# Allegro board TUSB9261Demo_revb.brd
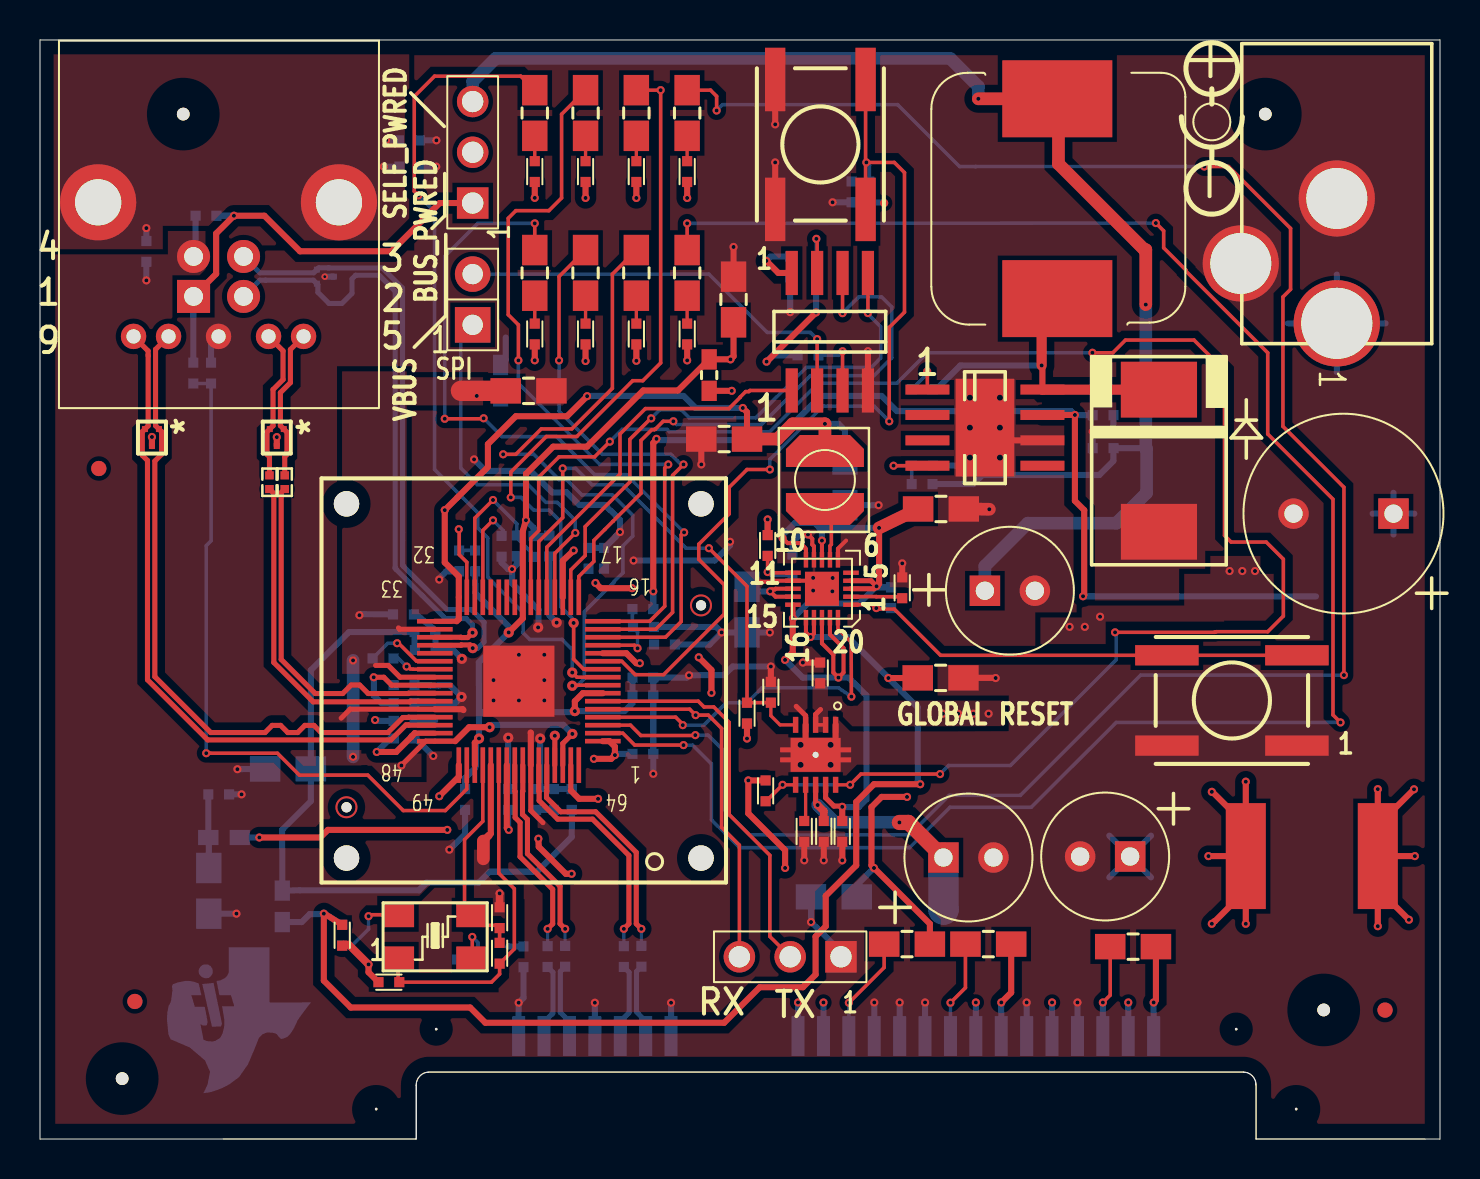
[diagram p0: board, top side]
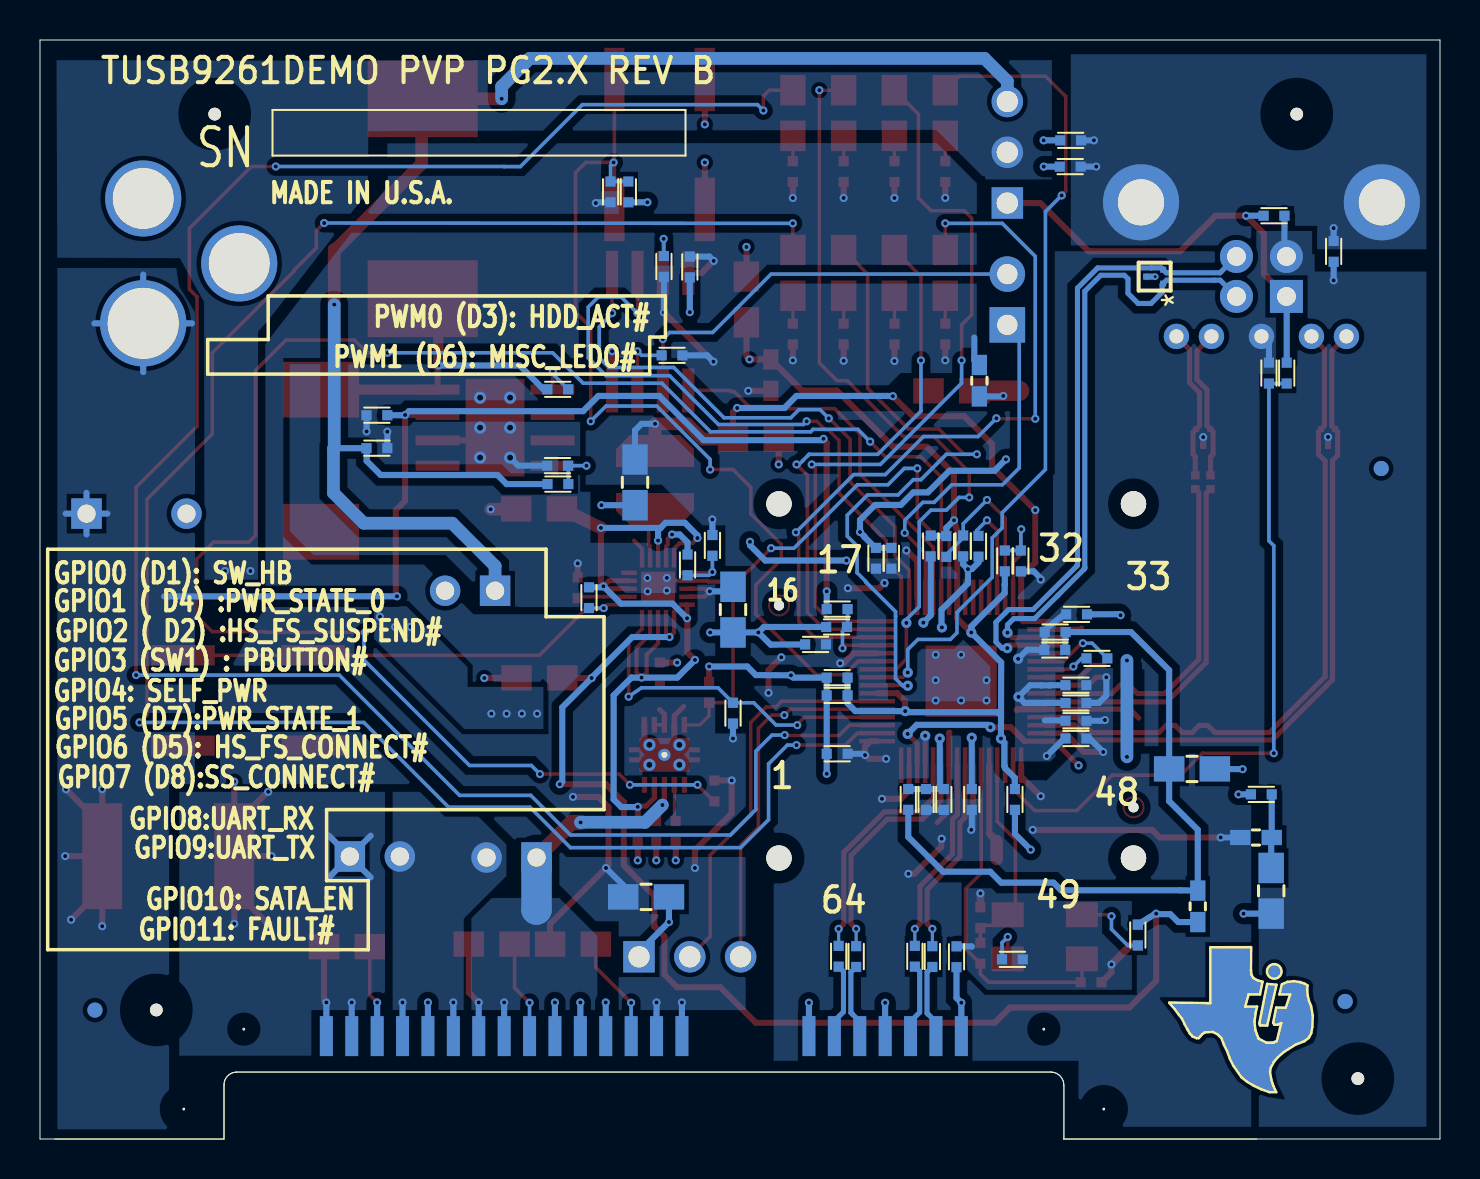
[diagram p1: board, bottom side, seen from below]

Outline 70 x 55 mm; copper layers: TOP, BOTTOM. Coordinates in mm from the lower left corner of the outline.
Outline path: 0,55 0,0 18.81,0 18.81,2.69 arc(18.98,3.14) 19.42,3.35 60.18,3.35 arc(60.62,3.16) 60.79,2.72 60.79,0 70,0 70,55 0,55

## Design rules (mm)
net group DIFFPAIR0: nets CAP_SSTXM CAP_SSTXP
net group DIFFPAIR1: nets SSTXM SSTXP
net group DIFFPAIR2: nets SSRXM SSRXP
net group DIFFPAIR3: nets CAP_SATARXM CAP_SATARXP
net group DIFFPAIR4: nets SATARXM SATARXP
net group DIFFPAIR5: nets CAP_SATATXM CAP_SATATXP
net group DIFFPAIR6: nets SATATXM SATATXP
net group DIFFPAIR7: nets US_DM US_DP

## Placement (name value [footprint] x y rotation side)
C1  0.01uF  [0402]  25.38 9.13 90 bottom
C2  0.01uF  [0402]  26.26 9.15 90 bottom
C6  0.01uF  [0402]  29.19 9.13 90 bottom
C7  0.01uF  [0402]  30.07 9.15 90 bottom
C8  22uF  [0805]  39.7 12.12 180 bottom
C10  220uF  [THCAP_2P5MM]  45.17 14.09 0 top
C11  0.1uF  [0402]  37.51 43.64 270 bottom
C12  220uF  [THCAP_2P5MM]  54.51 14.14 180 top
C13  0.1uF  [0201]  12.24 32.87 270 top
C14  0.1uF  [0201]  11.47 32.87 270 top
C15  .1uF  [0402]  5.32 44.42 90 bottom
C16  .001uF  [0402]  18.47 49.98 180 bottom
C17  18pF  [0402]  17.44 7.85 180 top
C18  0.1uF  [0402]  15.11 10.2 270 top
C19  18pF  [0402]  22.98 11.08 90 top
C20  18pF  [0402]  40.58 47.4 90 bottom
C21  220uF  [THCAP_2P5MM]  47.24 27.44 0 top
C22  0.01uF  [0402]  53.16 34.57 0 bottom
C23  0.01uF  [0402]  44.11 37.52 0 bottom
C24  22uF  [0805]  34.68 42.01 90 top
C25  1uF  [0402]  25.46 29.68 270 bottom
C26  0.1uF  [0402]  21.25 16.99 270 bottom
C27  0.1uF  [0402]  30.14 23.09 0 bottom
C28  0.1uF  [0402]  30.14 22.2 0 bottom
C29  0.01uF  [0402]  53.16 36.22 180 bottom
C30  1000uF  [THCAP_5MM]  65.17 31.3 180 top
C31  0.1uF  [0402]  18.17 26.25 0 bottom
C32  22uF  [0805]  24.43 37.44 0 top
C33  22uF  [0805]  34.21 35.03 180 top
C34  1uF  [0402]  31.22 24.75 0 bottom
C35  0.1uF  [0402]  18.21 21.82 0 bottom
C36  0.1uF  [0402]  30.14 19.28 0 bottom
C37  0.1uF  [0402]  24.81 16.99 90 bottom
C38  0.01uF  [0402]  23.41 16.99 90 bottom
C39  0.1uF  [0402]  27.43 29.06 90 bottom
C40  0.1uF  [0402]  25.7 16.99 90 bottom
C41  0.1uF  [0402]  28.2 29.06 90 bottom
C42  0.01uF  [0402]  18.21 22.71 0 bottom
C43  0.1uF  [0402]  18.21 20.93 0 bottom
C44  0.1uF  [0402]  18.21 20.04 0 bottom
C45  1uF  [0402]  8.3 46.2 180 bottom
C46  22uF  [0805]  40.25 32.86 270 bottom
C54  0.1uF  [0402]  8.93 17.25 0 bottom
C57  22uF  [0805]  45.05 31.53 0 top
C58  0.1uF  [0402]  19.26 24.47 0 bottom
C59  0.01uF  [0402]  26.59 16.99 90 bottom
C60  22uF  [0805]  35.35 26.49 270 bottom
C61  1uF  [0402]  19.24 25.37 0 bottom
C62  22uF  [0805]  12.4 18.52 180 bottom
C63  22uF  [0805]  45.03 23.08 0 top
C64  22uF  [0805]  8.44 12.42 270 bottom
C66  0.1uF  [0402]  39.01 23.32 90 top
C67  0.1uF  [0402]  40.11 15.4 270 top
C68  0.1uF  [0402]  43.11 27.59 90 top
C69  0.1uF  [0402]  39.19 15.4 270 top
C72  30pF  [0402]  36.38 29.71 90 bottom
CN1  10031569-001LF  [CONN_10031569]  39.81 5.15 180 bottom
D1  LED Green 0805  [0805]  29.82 43.34 90 top
D2  LED Green 0805  [0805]  29.82 51.35 90 top
D3  LED Green 0805  [0805]  32.36 43.34 90 top
D4  LED Green 0805  [0805]  24.74 51.35 90 top
D5  LED Green 0805  [0805]  27.28 43.34 90 top
D6  LED Green 0805  [0805]  32.36 51.35 90 top
D7  LED Green 0805  [0805]  24.74 43.34 90 top
D8  LED Green 0805  [0805]  27.28 51.35 90 top
D12  MBRS540T3  [DIODE_SMC]  55.95 33.94 270 top
F1  PTC FUSE  [FUSE_2920L]  63.59 14.16 0 top
FB1  220 @ 100MHZ  [0603]  33.46 38.23 90 top
FB2  220 @ 100MHZ  [0603]  23.03 37.95 270 bottom
FB4  220 @ 100MHZ  [0603]  9.2 15.09 180 bottom
FB5  220 @ 100MHZ  [0603]  12.11 11.64 90 bottom
J1  NOPOP  [EPRT-HEAD-00001-0000]  40.05 9.12 180 top
J2  Conn USB3_B_AK  [USB3_TYPEB_AK4AA009]  7.68 42.17 180 top
J3  2.1mm x 5.5mm  [PJ-202AH]  64.84 40.82 180 top
J4  HDR  [EPRT-HEAD-00001-0000]  21.63 46.84 90 top
J13  HDR2X1 M .1  [HDR_2X1]  21.63 40.74 0 top
L1  15uH  [DR127]  50.87 47.06 270 top
L2  2.2uH  [IND_SM_VLCF_4X4X2MM]  39.25 32.98 90 top
NOREF  -  [unnamed]  7.16 51.29 0 top
NOREF#2  -  [#2]  -0.04 0 90 top
NOREF#3  -  [unnamed]  4.11 3.02 0 top
NOREF#4  -  [unnamed#3]  67.25 6.45 0 top
NOREF#5  -  [#2]  -0.04 55 0 top
NOREF#6  -  [#2]  5.76 -42.8 0 top
NOREF#7  -  [unnamed]  64.19 6.46 0 top
NOREF#8  -  [#2]  51.15 0 90 top
NOREF#9  -  [#2]  16.81 1.5 0 top
NOREF#10  -  [#2]  45.25 29.97 0 top
NOREF#11  -  [unnamed#3]  4.74 6.88 0 top
NOREF#12  -  [#2]  -0.04 0 90 top
NOREF#13  -  [unnamed]  61.26 51.29 0 top
NOREF#14  -  [#2]  50.44 16.59 0 top
NOREF#15  -  [#2]  18.81 0 0 top
NOREF#16  -  [#2]  16.81 1.5 0 top
NOREF#17  -  [unnamed#3]  2.94 33.55 0 top
NOREF#18  -  [unnamed#3]  4.74 6.88 180 bottom
NOREF#19  -  [unnamed#3]  67.25 6.45 180 bottom
NOREF#20  -  [unnamed#3]  2.94 33.55 180 bottom
NOREF#21  -  [#2]  9.86 6.64 180 bottom
R2  4.7K  [0402]  38.4 39.22 0 bottom
R3  4.7K  [0402]  38.8 43.66 90 bottom
R4  10K  [0402]  17.15 24.05 0 bottom
R5  NOPOP  [0402]  23.08 29.66 90 bottom
R6  90.9K  [0402]  7.66 38.33 270 bottom
R7  10K  [0402]  8.55 38.33 270 bottom
R8  NOPOP  [0402]  22.98 9.3 90 top
R9  1M  [0402]  18.49 48.66 0 bottom
R10  4.7K  [0402]  24.68 29.65 90 bottom
R11  NOPOP  [0402]  23.84 29.68 270 bottom
R12  NOPOP  [0402]  21.76 28.93 270 bottom
R13  4.7K  [0402]  20.96 28.93 270 bottom
R14  330  [0402]  29.82 40.29 90 top
R15  330  [0402]  29.82 48.41 90 top
R16  330  [0402]  32.36 40.29 90 top
R17  4.7K  [0402]  41.47 47.4 90 bottom
R18  330  [0402]  24.74 48.41 90 top
R19  330  [0402]  27.28 40.29 90 top
R20  330  [0402]  32.36 48.41 90 top
R21  330  [0402]  24.74 40.29 90 top
R22  330  [0402]  27.28 48.41 90 top
R23  NOPOP  [0402]  15.11 10.21 270 bottom
R24  3.65K  [0402]  30.17 25.63 0 bottom
R25  10K  [0402]  30.14 26.52 180 bottom
R26  10K  [0402]  44.11 32.77 0 bottom
R27  3.16K  [0402]  44.13 33.7 180 bottom
R30  400K  [0402]  36.38 29.7 270 top
R31  475K  [0402]  37.62 28.73 270 bottom
R32  4.7K  [0402]  35.35 21.31 270 bottom
R33  10K  [0402]  36.28 17.42 270 top
R34  NOPOP  [0402]  35.35 21.31 270 top
R35  4.7K  [0402]  36.54 22.36 90 top
R36  27.4K  [0402]  38.21 15.4 270 top
R37  NOPOP  [0402]  21.38 8.99 180 bottom
R38  NOPOP  [0402]  24.17 9.12 270 bottom
R39  4.7K  [0402]  42.55 27.09 270 bottom
R40  10  [0805]  43.35 9.76 180 top
R41  10  [0805]  47.42 9.76 180 top
R42  10  [0805]  54.65 9.63 180 top
SW1  PB_SWITCH  [SW_MOM_2NO]  39.02 49.77 0 top
SW2  PB_SWITCH  [SW_MOM_2NO]  59.59 21.95 90 top
U2  Pm25LV512A  [SOIC_8S]  39.49 40.4 90 top
U3  TPS5450  [DDA_R-PDSO-G8]  47.25 35.6 0 top
U4  TPS650061  [RUK_S-PQFP-N20]  39.1 27.54 180 top
U5  TUSB9260APVP  [IRONWOOD_64PIN_C9508]  33.05 14.06 180 top
U7  TPS2560DRC  [DRC_S_PVSON_N10]  38.78 19.23 270 top
U10  TPD2EUSB30  [DRT_R_PDSO_N3_SOT23]  5.6 35.1 180 top
U11  TPD2EUSB30  [DRT_R_PDSO_N3_SOT23]  11.84 35.1 180 top
U12  TPD2EUSB30  [DRT_R_PDSO_N3_SOT23]  14.27 43.16 90 bottom
XY1  X OR Y  [ECX-53B]  19.76 10.12 0 top

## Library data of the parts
C1 C2 C6-C8 C11 C13-C20 C22-C29 C31-C46 C54 C57-C64 C66-C69 C72 = CAP NP
C10 C12 C21 C30 = CAP POL
CN1 = 0876781001: User Part Number: P*
D1-D8 = DIODE
D12 = DIODE SCHOTTKY
F1 = FUSE
FB1 FB2 FB4 FB5 = FERRITE BEAD
J1 J4 = HDR3X1 M .1
J2 = USB3_TYPEB_CONNECTOR
J3 = BNC_2
J13 = HDR2X1 M .1
L1 L2 = INDUCTOR FERRITE
NOREF#4 NOREF#11 NOREF#17-NOREF#20 = -: User Part Number: D*
R2-R27 R30-R42 = R
SW1 SW2 = PB_SWITCH_0
U2 = Pm25LV512A
U3 = TPS5450_2
U4 = TPS650061_0
U5 = TUSB9260PAP_6
U7 = TPS2560DRC_1
U10-U12 = TPD2E009
XY1 = X OR Y

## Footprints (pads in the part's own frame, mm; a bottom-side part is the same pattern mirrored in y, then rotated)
0201
  rect 0.406x0.432 smd: 1(-0.343,0) 2(0.343,0)
0402
  rect 0.508x0.508 smd: 1(-0.521,0) 2(0.521,0)
0603
  rect 1.016x0.762 smd: 1(-0.787,0) 2(0.787,0)
0805
  rect 1.524x1.27 smd: 1(-1.143,0) 2(1.143,0)
CONN_10031569
  round 0.127 hole 1.95 unplated: (-23,-3.65) (23,-3.65)
  round 0.127 hole 1.2 unplated: (-20,0.35) (20,0.35)
  rect 0.65x2 smd: P1(1.905,0) P2(0.635,0) P3(-0.635,0) P4(-1.905,0) P5(-3.175,0) P6(-4.445,0) P7(-5.715,0) P8(-6.985,0) P9(-8.255,0) P10(-9.525,0) P11(-10.795,0) P12(-12.065,0) P13(-13.335,0) P14(-14.605,0) P15(-15.875,0) S1(15.875,0) S2(14.605,0) S3(13.335,0) S4(12.065,0) S5(10.795,0) S6(9.525,0) S7(8.255,0)
DDA_R-PDSO-G8
  rect 2.2x0.5 smd: 1(-2.875,1.905) 2(-2.875,0.635) 3(-2.875,-0.635) 4(-2.875,-1.905) 5(2.875,-1.905) 6(2.875,-0.635) 7(2.875,0.635) 8(2.875,1.905)
  rect 2.94x4.89 smd: 9(0,0)
DIODE_SMC
  rect 2.794x3.81 smd: 1(3.556,0) 2(-3.556,0)
DR127
  rect 3.85x5.5 smd: 1(-5,0) 2(5,0)
DRC_S_PVSON_N10
  rect 0.8x0.27 smd: 1(-1.5,1) 2(-1.5,0.5) 3(-1.5,0) 4(-1.5,-0.5) 5(-1.5,-1) 6(1.5,-1) 7(1.5,-0.5) 8(1.5,0) 9(1.5,0.5) 10(1.5,1)
  round 0.61 hole 0.305: 11(0,0)
DRT_R_PDSO_N3_SOT23
  rect 0.3x0.3 smd: 1(-0.35,-0.425) 2(0.35,-0.425) 3(0,0.425)
ECX-53B
  rect 1.6x1.245 smd: 1(-1.854,-1.105) 2(1.854,-1.105) 3(1.854,1.105) 4(-1.854,1.105)
EPRT-HEAD-00001-0000
  rect 1.575x1.575 hole 1.067: 1(0,0)
  round 1.575 hole 1.067: 2(2.54,0) 3(5.08,0)
FUSE_2920L
  rect 2x5.3 smd: 1(-3.3,0) 2(3.3,0)
HDR_2X1
  rect 1.778x1.778 hole 1.016: 1(0,0)
  round 1.778 hole 1.016: 2(0,2.54)
IND_SM_VLCF_4X4X2MM
  custom 0.4x0.4 smd: 1(-1.45,0) 2(1.45,0)
IRONWOOD_64PIN_C9508
  round 1.27 hole 1.608 unplated: (0,0) (0,-17.725) (17.725,0) (17.725,-17.725)
  round 0.508 hole 0.848 unplated: (0,-12.646) (17.725,-2.54)
  rect 1.78x0.23 smd: 1(4.91,-5.85) 2(4.91,-6.25) 3(4.91,-6.65) 4(4.91,-7.05) 5(4.91,-7.45) 6(4.91,-7.85) 7(4.91,-8.25) 8(4.91,-8.65) 9(4.91,-9.05) 10(4.91,-9.45) 11(4.91,-9.85) 12(4.91,-10.25) 13(4.91,-10.65) 14(4.91,-11.05) 15(4.91,-11.45) 16(4.91,-11.85) 33(13.31,-11.85) 34(13.31,-11.45) 35(13.31,-11.05) 36(13.31,-10.65) 37(13.31,-10.25) 38(13.31,-9.85) 39(13.31,-9.45) 40(13.31,-9.05) 41(13.31,-8.65) 42(13.31,-8.25) 43(13.31,-7.85) 44(13.31,-7.45) 45(13.31,-7.05) 46(13.31,-6.65) 47(13.31,-6.25) 48(13.31,-5.85)
  rect 0.23x1.78 smd: 17(6.11,-13.05) 18(6.51,-13.05) 19(6.91,-13.05) 20(7.31,-13.05) 21(7.71,-13.05) 22(8.11,-13.05) 23(8.51,-13.05) 24(8.91,-13.05) 25(9.31,-13.05) 26(9.71,-13.05) 27(10.11,-13.05) 28(10.51,-13.05) 29(10.91,-13.05) 30(11.31,-13.05) 31(11.71,-13.05) 32(12.11,-13.05) 49(12.11,-4.65) 50(11.71,-4.65) 51(11.31,-4.65) 52(10.91,-4.65) 53(10.51,-4.65) 54(10.11,-4.65) 55(9.71,-4.65) 56(9.31,-4.65) 57(8.91,-4.65) 58(8.51,-4.65) 59(8.11,-4.65) 60(7.71,-4.65) 61(7.31,-4.65) 62(6.91,-4.65) 63(6.51,-4.65) 64(6.11,-4.65)
  rect 3.56x3.56 smd: 65(9.11,-8.85)
PJ-202AH
  round 4.318 hole 3.556: 1(0,0)
  round 3.81 hole 3.048: 2(4.801,-2.997) 3(0,-6.248)
RUK_S-PQFP-N20
  rect 0.78x0.22 smd: 1(-1.45,0.8) 2(-1.45,0.4) 3(-1.45,0) 4(-1.45,-0.4) 5(-1.45,-0.8) 11(1.45,-0.8) 12(1.45,-0.4) 13(1.45,0) 14(1.45,0.4) 15(1.45,0.8)
  rect 0.22x0.78 smd: 6(-0.8,-1.45) 7(-0.4,-1.45) 8(0,-1.45) 9(0.4,-1.45) 10(0.8,-1.45) 16(0.8,1.45) 17(0.4,1.45) 18(0,1.45) 19(-0.4,1.45) 20(-0.8,1.45)
  rect 1.7x1.7 smd: 21(0,0)
SOIC_8S
  rect 2.21x0.61 smd: 1(-2.94,1.905) 2(-2.94,0.635) 3(-2.94,-0.635) 4(-2.94,-1.905) 5(2.94,-1.905) 6(2.94,-0.635) 7(2.94,0.635) 8(2.94,1.905)
SW_MOM_2NO
  rect 1.016x3.175 smd: 1(-2.261,-3.251) 2(-2.261,3.251) 3(2.261,-3.251) 4(2.261,3.251)
THCAP_2P5MM
  rect 1.524x1.524 hole 0.914: 1(0,0)
  round 1.524 hole 0.914: 2(2.5,0)
THCAP_5MM
  rect 1.524x1.524 hole 0.914: 1(-2.5,0)
  round 1.524 hole 0.914: 2(2.5,0)
unnamed
  round 0.635 hole 3.175 unplated: (0,0)
unnamed#3
  round 0.762 smd: 1(0,0)
USB3_TYPEB_AK4AA009
  rect 1.651x1.651 hole 0.94: 1(0,0)
  round 1.651 hole 0.94: 2(-2.5,0) 3(-2.5,-2) 4(0,-2)
  round 1.27 hole 0.711: 5(-5.5,2) 6(-3.75,2) 7(-1.25,2) 8(1.25,2) 9(3,2)
  round 3.81 hole 2.311: 10(-7.27,-4.71) 11(4.77,-4.71)

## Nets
AGND: C8.2 C10.2 C11.2 C12.2 C15.1 C16.1 C20.1 C21.2 C22.1 C24.2 C25.2 C26.2 C27.2 C28.2 C29.1 C30.2 C31.2 C32.2 C33.2 C34.2 C35.2 C36.2 C37.2 C38.2 C39.2 C40.2 C41.2 C42.2 C43.2 C44.2 C45.2 C46.2 C54.2 C57.2 C58.2 C59.2 C60.2 C61.2 C62.2 C63.2 C64.2 C66.2 C67.2 C68.2 C69.2 CN1.P4(GND#P4) CN1.P5(GND#P5) CN1.P6(GND#P6) CN1.P10(GND#P10) CN1.P12(GND#P12) CN1.S1(GND#S1) CN1.S4(GND#S4) CN1.S7(GND#S7) D12.1(ANODE) J1.1 J2.4(GND#4) J2.7(GND#7) J3.2(S) J3.3(SW) R5.1 R7.1 R9.2 R11.2 R13.2 R24.2 R27.1 R31.1 R35.2 R36.2 R38.2 SW1.1(A) SW1.2(A_) SW2.1(A) SW2.2(A_) U2.4(GND) U3.6(GND#6) U3.9(GND#9) U4.6(PGND) U4.9(MODE) U4.12(AGND) U4.21(PWR_PAD) U5.44(NC2) U5.58(NC3) U5.65(VSS) U7.1(GND) U7.4(EN1) U7.11(PAD) U10.3(GND) U11.3(GND) U12.3(GND)
GND_EARTH: C15.2 C16.2 J2.10(SHIELD0) J2.11(SHIELD1) R9.1
VBUS: C45.1 J2.1(VBUS) J4.1 R6.1
VDD_1P1V: C33.1 C34.1 C35.1 C36.1 C37.1 C38.1 C39.1 C40.1 C41.1 C42.1 C43.1 C44.1 C46.1 C72.2 FB4.1 L2.2 R30.1 U5.1(VDD#1) U5.12(VDD#12) U5.19(VDD#19) U5.32(VDD#32) U5.33(VDD#33) U5.41(VDD#41) U5.47(VDD#47) U5.49(VDD#49) U5.55(VDD#55) U5.61(VDD#61) U5.63(VDD#63)
VDD_3P3V: C24.1 C25.1 C26.1 C27.1 C28.1 FB1.2 R10.2 R12.2 U5.7(VDDSHV#7) U5.24(VDDSHV#24) U5.51(VDD33)
VDDA_1P8V: C58.1 C59.1 C61.1 C62.1 FB5.2
VDDA_3P3V: C31.1 C32.1 FB2.2 U5.34(VDDA33#34) U5.40(VDDA33#40) U5.48(VDDA33#48) U5.62(VDDA33#62)
VSSOSC: C17.2 C18.2 C19.2 R37.2 R38.1 U5.53(VSSOSC)
BOARD_1P8V: C18.1 C63.1 FB5.1 R23.1 U4.16(FB_LDO2) U4.17(VLDO2)
BOARD_3P3V: C8.1 C11.1 C60.1 CN1.P1(V33#P1) CN1.P2(V33#P2) FB1.1 FB2.1 R2.1 R3.1 R14.1 R15.1 R16.1 R17.1 R18.1 R19.1 R20.1 R21.1 R22.1 R32.2 R33.1 R34.2 R40.1 U2.8(VCC) U4.13(FB_LDO1) U4.14(VLDO1)
BOARD_5V: C57.1 C67.1 R39.1 U4.3(EN_LDO1) U4.4(EN_LDO2) U4.8(VINDCDC) U4.10(EN_DCDC) U4.15(VINLDO1) U4.18(VINLDO2) U4.19(RSTSNS) U7.9(OUT1)
BOARD_12V: C29.2 C30.1 F1.2 J3.1(T) R25.1 U3.7(VIN)
BOOT: C23.1 U3.1(BOOT)
CAP_SATARXM: C6.1 CN1.S5(B-)
CAP_SATARXP: C7.1 CN1.S6(B+)
CAP_SATATXM: C1.1 CN1.S2(A+)
CAP_SATATXP: C2.1 CN1.S3(A-)
CAP_SSTXM: C13.1 J2.5(SSTXN) U11.1(D+)
CAP_SSTXP: C14.1 J2.6(SSTXP) U11.2(D-)
CN_VBUS: R6.2 R7.2 U5.50(USB_VBUS)
FAULT#: R33.2 U5.23(SPI_CS2_GPIO11) U7.6(FAULT2Z) U7.10(FAULT1Z)
FB_DCDC: C72.1 R30.2 R31.2 U4.11(FB_DCDC)
FREQSEL0: R10.1 R11.1 U5.30(FREQSEL0)
FREQSEL1: R12.1 R13.1 U5.31(FREQSEL1)
FUSE_12V: C12.1 CN1.P14(V12#P14) CN1.P15(V12#P15) F1.1 R42.1
GRST#: R32.1 U4.20(RST#) U5.4(GRSTZ)
HDD_ACT#: D3.2(K) U5.2(PWM0)
HS_FS_CONNECT#: D5.2(K) U5.15(GPIO6)
HS_FS_SUSPEND#: D2.2(K) U5.10(GPIO2)
ILIM1: R36.1 U7.7(ILIM)
MISC_LED0#: D6.2(K) U5.3(PWM1)
MR#: R39.2 SW2.3(B_) SW2.4(B) U4.1(MR#)
PBUTTON#: C20.2 R17.2 SW1.3(B_) SW1.4(B) U5.11(GPIO3)
PH: C23.2 D12.2(CATHODE) L1.2 U3.8(PH)
PWR_STATE_0: D4.2(K) U5.9(GPIO1)
PWR_STATE_1: D7.2(K) U5.14(GPIO5)
REG_5V: C21.1 C22.2 J4.3 L1.1 R26.2
SATA_5V: C10.1 C69.1 CN1.P8(V5#P8) CN1.P9(V5#P9) R41.1 U7.8(OUT2)
SATA_EN: R34.1 R35.1 U5.22(SPI_CS1_GPIO10) U7.5(EN2)
SATARXM: C6.2 U5.59(SATA_RXM)
SATARXP: C7.2 U5.60(SATA_RXP)
SATATXM: C1.2 U5.56(SATA_TXM)
SATATXP: C2.2 U5.57(SATA_TXP)
SELF_PWR: R24.1 R25.2 U5.13(GPIO4)
SOURCE_5V: C66.1 J4.2 U7.2(IN#2) U7.3(IN#3)
SPI_CE#: U2.1(CE#) U5.21(SPI_CS0)
SPI_SCK: U2.6(SCK) U5.17(SPI_SCLK)
SPI_SI: J13.1 U5.20(SPI_DATA_OUT)
SPI_SO: U2.5(SI) U5.18(SPI_DATA_IN)
SPI_SO_J: J13.2 U2.2(SO)
SS_CONNECT#: D8.2(K) U5.16(GPIO7)
SSRXM: J2.8(SSRXN) U5.45(USB_SSRXM) U10.1(D+)
SSRXP: J2.9(SSRXP) U5.46(USB_SSRXP) U10.2(D-)
SSTXM: C13.2 U5.42(USB_SSTXM)
SSTXP: C14.2 U5.43(USB_SSTXP)
SW_1.1V: L2.1 U4.7(SW)
SW_HB: D1.2(K) U5.8(GPIO0)
TRST: C68.1 U4.2(TRST)
UART_RX: J1.3 U5.5(UART_RX_GPIO8)
UART_TX: J1.2 U5.6(UART_TX_GPIO9)
US_DM: J2.2(DM) U5.35(USB_DM) U12.1(D+)
US_DP: J2.3(DP) U5.36(USB_DP) U12.2(D-)
USB2_1P1V: C54.1 C64.1 FB4.2
USB_R1: R4.1 U5.38(USB_R1)
USB_R1RTN: R4.2 U5.39(USB_R1RTN)
VSENSE: R26.1 R27.2 U3.4(VSENSE)
XI: C19.1 R8.2 U5.52(XI) XY1.3(XI)
XO: C17.1 R8.1 U5.54(XO) XY1.1(XO)
N50426: R3.2 U2.7(HOLD#)
N52215: R2.2 U2.3(WP#)
N191797: R5.2 U5.29(JTAG_TRSTZ)
N372931: D1.1(A) R14.2
N373403: D4.1(A) R18.2
N373877: D7.1(A) R21.2
N388253: D2.1(A) R15.2
N388277: D5.1(A) R19.2
N388301: D8.1(A) R22.2
N389292: D3.1(A) R16.2
N389316: D6.1(A) R20.2
N815346: R23.2 XY1.4(VCC)
N990729: R37.1 XY1.2(GND)
N1011037: CN1.P3(V33#P3) R40.2
N1019902: CN1.P7(V5#P7) R41.2
N1022218: CN1.P13(V12#P13) R42.2

Pads without a net: CN1 P11; NOREF#4 1; NOREF#11 1; NOREF#17 1; NOREF#18 1; NOREF#19 1; NOREF#20 1; U3 2 3 5; U4 5; U5 25 26 27 28 37 64

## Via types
v1: diameter 0.406, hole 0.203, TOP to BOTTOM, 224 vias
v2: diameter 0.33, hole 0.152, TOP to BOTTOM, 1 via
v3: diameter 0.508, hole 0.206, TOP to BOTTOM, 17 vias
v4: diameter 0.61, hole 0.305, TOP to BOTTOM, 10 vias

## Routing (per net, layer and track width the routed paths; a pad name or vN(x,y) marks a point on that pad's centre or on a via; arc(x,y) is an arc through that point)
AGND: length 145.9
  TOP w0.203: 35.99,27.89 36.59,27.89 36.64,27.94 U4.12 38.37,27.94 ; U4.9 38.7,29.67 38.62,29.75 38.62,30.04 v1(38.4,30.25) ; 40.3,29.95 39.9,29.54 U4.6
  TOP w0.254: U5.58 24.54,16.44 25.15,15.83 ; U7.4 38.28,21.19 37.81,21.65 ; U5.44 15.51,21.51 15.06,21.06
  TOP w0.305: 24.53,20.34 24.54,20.33 U5.58 ; U7.4 38.28,19.98 v4(38.03,19.73) ; U11.3 v1(11.84,35.13) ; C68.2 v1(43.11,28.81) ; 21.17,21.47 21.13,21.51 U5.44 ; C69.2 v1(39.19,13.95) ; R35.2 v1(36.54,23.65) ; v1(36.76,48.87) SW1.1 ; C66.2 v1(38.14,23.84) ; SW1.2 v1(36.76,50.78) ; U10.3 v1(5.6,35.13) ; C33.2 v1(33.06,33.76) ; C67.2 v1(40.11,13.95) ; R36.2 v1(38.21,13.95) ; v4(39.53,19.73) 39.78,19.98 U7.1 ; v1(47.78,23.07) 47.78,23.08 C63.2 ; v1(39.62,27.41) 39.56,27.47 U4.21 38.75,27.54 v1(38.66,27.45) ; U3.6 48.63,34.96 v4(48,35.6) ; U2.4 v1(41.4,39.42) ; C24.2 v1(34.68,44.64)
  TOP w0.635: C57.2 v1(47.47,31.52)
  BOTTOM w0.305: CN1.S7 v1(31.55,6.82) ; C25.2 25.46,26.21 v3(25.83,25.84) 25.76,25.77 ; J2.7 8.55,39.79 R7.1 ; C45.2 7.78,44.27 J2.4 ; C34.2 33.47,24.74 v1(34.08,25.35) ; CN1.P6 v1(44.25,6.83) ; v3(25.01,20.04) 25.01,17.72 C37.2 C40.2 C59.2 ; v1(34.08,25.35) 33.8,25.63 R24.2 ; v1(34.08,25.35) C60.2 v1(36.49,25.35) ; CN1.P4 v1(41.71,6.83) ; CN1.P12 v1(51.87,6.83) ; U12.3 v2(14.24,43.16) ; CN1.P5 v1(42.98,6.83) ; R9.2 v1(19.81,48.66) ; C46.2 v1(41.93,31.72) ; C31.2 18.81,26.25 19.76,25.47 C61.2 C58.2 20.64,24.49 v3(21.09,24.03) ; C11.2 v1(37.51,41.38) ; v1(29.68,28.95) 33.74,28.95 34.5,29.71 v1(34.5,29.89) ; R27.1 46.09,33.7 v4(46.5,34.1) ; C43.2 18.75,20.95 19.76,20.95 ; C8.2 v1(38.55,10.86) 40.05,9.36 J1.1 ; C16.1 v1(19.82,49.98) ; C20.1 v1(39.63,46.88) ; CN1.S4 v1(27.74,6.82) ; C39.2 C41.2 28.23,29.58 28.78,30.13 28.78,30.16 v1(29,30.38) 29,30.98 28.25,31.73 26.96,31.73 26.33,32.36 25.61,32.36 24.53,33.44 22.27,33.44 v1(21.7,34.01) ; R31.1 37.62,29.86 38.02,30.25 v1(38.4,30.25) ; v1(23.6,28.52) 23.6,27.81 24.92,26.49 24.92,25.6 v3(24.91,25.6) ; v1(23.6,28.52) 23.41,28.52 23.08,28.85 R5.1 ; v1(23.6,28.52) 23.84,28.76 R11.2 ; 8.3,11.28 C64.2 v1(9.82,11.28) ; v1(30.66,18.28) C36.2 C28.2 C27.2 32.34,23.09 v1(32.45,23.21) 34.21,23.22 34.64,23.65 v1(36.54,23.65) ; C54.2 v1(10.08,17.25) ; v1(19.66,19.17) 18.79,20.04 C44.2 ; C15.1 v1(5.32,42.97) ; v1(20.47,14.48) 21.25,15.27 C26.2 ; v1(53.67,35.41) 53.67,36.22 C29.1 ; CN1.S1 v1(23.93,6.82) 24.17,7.06 R38.2 ; C42.2 19.5,22.71 19.51,22.7 19.94,22.7 19.95,22.71 20.49,22.71 v3(21.08,22.12) 20.77,21.82 C35.2 ; CN1.P10 v1(49.33,6.83) ; R13.2 20.32,28.41 19.96,28.05 v1(19.96,28) ; C38.2 v3(23.41,20.08) ; C22.1 v1(52.63,35.4) ; C62.2 v1(9.87,18.51)
  vias: v1(22.68,22.96) v1(22.68,21.95) v1(23.95,24.23) v1(23.95,21.95) v1(25.22,24.23) v1(25.22,22.96) v1(25.22,21.95) v1(38.66,28.08) v1(39.63,28.08) v4(38.03,18.73) v4(39.53,18.73) v4(46.5,37.1) v4(46.5,35.6) v4(48,37.1) v4(48,34.1)
GND_EARTH: length 2.1
  BOTTOM w0.305: R9.1 v1(17.19,48.66) ; C16.2 v1(17.3,49.98) ; C15.2 v1(5.32,45.58)
VBUS: length 22.7
  TOP w0.305: J2.1 8.81,43.3 8.81,45.32 v1(9.7,46.2) 11.22,46.2 13,44.43 17.57,44.43 19.98,46.84 J4.1
  BOTTOM w0.305: C45.1 v1(9.7,46.2) ; J2.1 7.66,42.15 R6.1
VDD_1P1V: length 83.6
  TOP w0.254: v1(16.69,23.11) 17.19,23.11 17.59,22.71 U5.41 ; 18.74,20.31 U5.47 ; U5.33 20.83,25.91 ; U5.61 v3(25.74,20.18) ; U5.63 26.54,17.44
  TOP w0.305: v1(27.9,17.02) 26.96,17.02 26.54,17.44 ; v1(32.94,24.11) 33.57,23.47 v1(33.57,22.33) ; U5.49 20.94,18.13 v1(19.96,17.15) ; v1(23.44,15.47) 23.34,15.57 U5.55 ; v1(26.58,13.27) 26.29,13.27 24.94,14.62 v1(24.92,15.03) ; U5.12 29.32,24.31 29.82,23.81 v1(29.99,23.81) ; U5.1 28.47,19.91 28.75,19.64 v1(28.75,19.21) 28.56,19.03 v1(27.69,19.03) ; v1(20.36,15.47) 14.4,15.47 14.01,15.09 v1(10.97,15.09) ; v1(29.61,27.57) 28.04,27.57 v1(27.77,27.83) ; C33.1 35.35,36.37 v1(35.14,36.58) ; U5.19 26.14,28.94 v1(26.68,29.45) ; v1(16.84,19.37) 17.81,19.37 18.57,20.13 18.57,20.14 18.73,20.3 18.74,20.3 18.74,20.31 ; v1(27.36,37.17) 26.35,36.17 23.79,36.17 22.4,34.77 22.4,33.63 20.87,32.11 20.87,32.11 v1(20.24,31.47) 20.24,28.85 20.94,28.15 U5.32 20.94,26.02 20.83,25.91 ; R30.1 v1(36.38,31.01)
  TOP w0.635: C33.1 36.87,35.03 37.64,35.79 v1(39.25,35.79) L2.2
  BOTTOM w0.305: C46.1 40.25,35.46 39.92,35.79 v1(39.25,35.79) ; v1(16.69,23.11) 16.69,22.2 17.06,21.82 C35.1 ; C36.1 28.81,19.28 v1(28.75,19.21) ; v1(27.36,37.17) 27.36,37.18 27.6,37.18 27.6,37.19 32.18,37.19 32.78,36.58 v1(35.14,36.58) ; C40.1 C37.1 ; C43.1 16.96,20.93 v1(16.75,20.97) ; C72.2 36.38,31 v1(36.38,31.01) ; C44.1 17.51,20.04 v1(16.84,19.37) ; 30,23.81 v1(29.99,23.81) ; C38.1 23.41,15.5 v1(23.44,15.47) ; FB4.1 v1(10.97,15.09)
VDD_3P3V: length 49.7
  TOP w0.305: v3(21.95,20.04) 21.74,19.83 U5.51 ; v3(26.74,21.41) 26.74,21.91 27.14,22.31 U5.7 ; v3(23.44,25.35) 24.14,26.05 U5.24 24.14,30.42 v1(24.3,30.97) 24.3,33.29 25.66,34.65 27.35,34.65 30.16,37.46 31.9,37.46 FB1.2 v1(34.52,39.02) 34.68,39.17 C24.1
  BOTTOM w0.305: 21.95,21.19 22.12,21.36 26.69,21.36 v3(26.74,21.41) 29.23,21.41 29.62,21.81 C28.1 C27.1 ; 21.95,21.19 21.94,23.85 v3(23.44,25.35) 23.44,25.65 21.77,27.32 21.77,27.75 21.76,27.75 R12.2 ; 21.95,21.19 v3(21.95,20.04) 21.95,19.99 21.79,19.83 21.79,18.68 21.75,18.65 21.75,18.57 21.25,18.07 C26.1 ; C25.1 R10.2 24.68,30.58 v1(24.3,30.97)
VDDA_1P8V: length 35.4
  BOTTOM w0.305: C58.1 C61.1 15.45,25.37 13.54,23.46 C62.1 13.54,16.91 12.11,15.48 FB5.2 13,12.45 18.94,12.45 19.32,12.83 21.94,12.83 22.49,13.38 24.85,13.38 26.59,15.12 C59.1
VDDA_3P3V: length 26.4
  TOP w0.254: 17.92,25.58 17.99,25.51 U5.34 ; 20.76,19.91 U5.48 19.28,19.91 18.07,18.7 v1(18.07,18.69) ; 16.78,23.7 17.41,23.7 18,23.11 U5.40 ; v3(26.62,20.27) 26.14,19.8 U5.62
  TOP w0.305: 20.76,19.91 21.46,20.61 v3(22.48,20.61)
  TOP w1.016: C32.1 21.05,37.44
  BOTTOM w0.305: v3(26.62,20.27) 26.16,20.73 22.6,20.73 v3(22.48,20.61) ; v1(21.84,37.19) 21.86,37.16 FB2.2 ; v1(15.97,26.21) 16.02,26.27 C31.1
  BOTTOM w0.635: v1(15.65,23.95) v1(15.65,19.13)
VSSOSC: length 9.1
  TOP w0.305: C17.2 16.43,8.35 v1(16.43,8.74) ; U5.53 22.54,15.28 22.44,15.18
  TOP w0.381: C18.2 15.16,9.72 15.44,9.72 v1(16.43,8.74) ; C19.2 v1(22.98,12.3) ; 22.17,14.91 22.44,15.18
  TOP w0.635: 22.17,14.02 22.17,14.91
  BOTTOM w0.305: 23.41,9.63 23.42,9.64 R38.1
BOARD_1P8V: length 61.6
  TOP w0.203: U4.17 38.7,25.29 v1(38.53,25.12) 38.3,25.35 U4.16
  TOP w0.305: v1(44.01,17.76) 41.7,17.76 40.81,16.87 40.81,13.69 39.29,12.17 39.29,10.64 38.78,10.14 38.78,8.23 38.14,7.6 35.99,7.6 34.21,5.82 22.27,5.82 21.51,6.58 15.54,6.58 14.19,7.93 v1(14.19,11.28) 14.2,11.29 C18.1 ; v1(42.42,23.07) 43.88,23.07 C63.1
  BOTTOM w0.305: v1(44.01,17.76) 43.89,17.88 43.89,21.6 v1(42.42,23.07) 42.42,23.09 40.38,25.12 v1(38.53,25.12) ; R23.1 14.5,11.11 14.27,11.25 14.22,11.25 v1(14.19,11.28) 14.17,11.25 14.1,11.25 14.1,11.25 13.48,11.25 13.09,10.86 FB5.1
BOARD_3P3V: length 46
  TOP w0.203: U4.13 36.78,27.54 36.74,27.5 36.6,27.5 v1(36.51,27.41) 36.78,27.14 U4.14
  TOP w0.305: R22.1 v1(27.28,47.09) ; R21.1 v1(24.74,38.97) ; R15.1 v1(29.82,47.09) ; v1(37.26,13.57) 37.26,14.45 35.41,16.29 v1(35.41,17.95) R33.1 ; FB1.1 v1(34.59,37.44) ; R14.1 v1(29.82,38.94) ; v1(36.33,38.9) 36.34,38.9 v1(38.8,41.37) ; R40.1 44.49,10.77 v1(41.7,13.57) 41.57,13.69 41.57,16.61 42.08,17.12 v1(43.35,17.12) ; R20.1 v1(32.36,47.09) ; v1(36.32,43.94) 36.92,43.34 U2.8 ; R19.1 v1(27.28,38.93) ; R18.1 v1(24.74,47.1) ; R16.1 v1(32.36,38.97) ; R34.2 v1(35.35,20.04)
  BOTTOM w0.305: C8.1 40.84,12.7 v1(41.7,13.57) ; v1(42.21,46.84) 42.17,46.88 R17.1 ; 23.29,40.11 23.29,38.99 FB2.1 ; CN1.P2 v1(39.17,6.83) ; C60.1 35.58,27.41 v1(36.51,27.41) ; R34.2 v1(35.35,20.04) ; v1(36.33,38.9) 36.65,39.22 R2.1 ; CN1.P1 v1(37.9,6.83) ; v1(36.32,43.94) 36.53,44.16 C11.1 ; R3.1 v1(38.8,41.37)
BOARD_5V: length 45.8
  TOP w0.203: U4.10 38.3,29.53 38.23,29.59 38.23,29.6 38.02,29.82 37.38,29.82 v1(37.13,30.08) ; v1(39.1,29.95) U4.8 ; U4.18 39.1,24.8 39.67,24.23 39.67,23.34 v1(39.92,23.09) 40.18,23.34 40.18,24.57 39.5,25.25 U4.19
  TOP w0.254: U4.4 41.55,27.94 v1(41.83,27.66) 41.7,27.54 U4.3 ; v1(40.11,16.63) 40.07,16.66 39.69,16.66 39.28,17.08 U7.9 ; U4.15 v1(37.65,26.06)
  TOP w0.305: v1(41.83,27.66) 41.95,27.79 v1(41.95,30.58) ; C67.1 v1(40.11,16.63) ; v1(37.65,26.06) 37.64,26.05 37.64,24.36 v1(37.25,23.98)
  TOP w0.635: C57.1 v1(41.95,30.58)
  BOTTOM w0.305: 38.97,30.58 39.1,30.46 v1(39.1,29.95) ; 38.97,30.58 v1(41.95,30.58) ; 38.97,30.58 38.72,30.84 37.76,30.84 37.13,30.21 v1(37.13,30.08) ; v1(37.65,26.06) 38.38,26.79 40.96,26.79 v1(41.83,27.66) 41.88,27.61 R39.1 ; v1(37.25,23.98) 38.14,23.09 v1(39.92,23.09) 40.43,23.09 41.32,22.2 41.32,16.99 40.94,16.61 40.12,16.61 v1(40.11,16.63)
BOARD_12V: length 81.7
  TOP w0.305: 66.89,12.53 v1(66.89,10.65) ; 66.89,12.53 F1.2 ; 66.89,12.53 v1(68.45,10.97) ; 66.89,15.69 v1(68.7,17.5) ; 66.89,15.69 v1(66.89,17.51) ; 66.89,15.69 F1.2 ; v1(52.15,27.16) 52.21,27.22 52.21,31.47 51.75,31.94 v1(51.75,36.23) U3.7 ; F1.2 v1(68.74,14.16) ; v1(30.82,35.04) 30.77,34.98 30.77,34.94 30.66,34.83 v1(30.66,27.41)
  BOTTOM w0.305: 64.84,38.38 J3.1 ; J3.1 67.28,40.82 ; J3.1 64.84,43.26 ; J3.1 62.4,40.82 ; R25.1 v1(30.66,27.41) ; 66.63,31.3 C30.1 ; C30.1 67.67,32.34 ; C30.1 67.67,30.25 ; C30.1 68.72,31.3 ; v1(30.82,35.04) 30.89,34.97 36.82,34.97 39.03,37.19 42.08,37.19 42.84,36.42 51.55,36.42 v1(51.75,36.23) 51.76,36.22 C29.2 ; 63.8,27.15 v1(52.15,27.16)
BOOT: length 2.2
  TOP w0.178: U3.1 44.37,37.51 44.37,38.41 v1(44.36,38.42)
  BOTTOM w0.178: C23.1 44.37,38.29 44.37,38.46 44.36,38.46 v1(44.36,38.42)
CAP_SATARXM: length 3.8
  BOTTOM w0.254: C6.1 29.46,8.34 29.46,6.33 29.4,6.27 29.01,5.88 CN1.S5
CAP_SATARXP: length 3.8
  BOTTOM w0.254: C7.1 29.83,8.38 29.83,6.36 30.28,5.91 CN1.S6
CAP_SATATXM: length 3.8
  BOTTOM w0.254: CN1.S2 25.2,5.86 25.59,6.24 25.65,6.3 25.65,8.34 C1.1
CAP_SATATXP: length 3.8
  BOTTOM w0.254: CN1.S3 26.47,5.88 26.02,6.34 26.02,8.38 C2.1
CAP_SSTXM: length 7.6
  TOP w0.254: C13.1 12.24,34.15 12.35,34.27 12.35,35.37 U11.1 12.02,35.7 12.02,37.35 12.52,37.85 12.52,39.51 J2.5
CAP_SSTXP: length 7.6
  TOP w0.254: C14.1 11.47,34.14 11.35,34.27 11.35,35.39 U11.2 11.65,35.69 11.65,37.5 12.15,38.01 12.15,39.44 J2.6
CN_VBUS: length 35.4
  TOP w0.178: U5.50 21.34,17.51 20.27,16.44 18.16,16.44 16.39,18.21 12.97,18.21 11.87,19.31 8.53,19.31 v1(8.31,19.31)
  BOTTOM w0.178: R6.2 R7.2 8.55,29.94 8.31,29.69 v1(8.31,19.31)
FAULT#: length 90.6
  TOP w0.165: U7.10 v1(40.51,17.73) ; v1(37.13,17.73) U7.6
  TOP w0.178: v1(53.75,25.36) 53.75,25.36 58.72,25.36 58.74,25.36 58.81,25.39 61.38,25.39 62.17,26.17 62.17,29.02 61.31,29.87 59.56,29.87 59.23,30.2 59.23,38.46 57.7,39.98 54.27,39.98 53.64,39.35 v1(52.62,39.35) ; U5.23 24.54,30.05 24.94,30.44 24.94,33.12 25.95,34.14 27.73,34.14 v1(28.49,34.9) ; v1(45,18.26) 41.04,18.26 v1(40.51,17.73) ; R33.2 36.31,16.9 v1(37.13,17.73)
  BOTTOM w0.178: v1(28.49,34.9) 29.11,35.51 31.35,35.51 31.47,35.39 36.48,35.39 38.91,37.82 41.7,37.82 42.84,37.82 44.37,39.35 v1(52.62,39.35) ; v1(53.75,25.36) 53.81,25.3 53.81,23.98 48.52,18.69 45.43,18.69 v1(45,18.26) ; v1(40.51,17.73) v1(37.13,17.73)
FB_DCDC: length 4.2
  TOP w0.178: R30.2 v1(36.38,28.37) 36.42,28.34 U4.11
  BOTTOM w0.178: R31.2 36.55,28.21 v1(36.38,28.37) 36.38,28.38 C72.1
FREQSEL0: length 8.9
  TOP w0.178: U5.30 21.74,31.07 v1(22.65,31.98)
  BOTTOM w0.178: v1(22.65,31.98) 23.84,30.79 R11.1 23.84,30.09 24.68,29.24 R10.1
FREQSEL1: length 5.4
  TOP w0.178: v1(20.94,30.52) 20.96,30.49 20.96,29.24 21.34,28.86 U5.31
  BOTTOM w0.178: R12.1 20.96,29.45 R13.1 20.96,30.49 v1(20.94,30.52)
FUSE_12V: length 25.9
  TOP w0.305: 60.29,15.7 F1.1 ; 60.29,15.7 58.62,17.38 v1(58.59,17.38) ; 60.29,15.7 v1(60.29,17.88) ; F1.1 60.29,12.44 ; F1.1 v1(58.42,14.16) ; 60.29,12.44 58.74,10.9 58.72,10.9 v1(58.59,10.77) ; 60.29,12.44 v1(60.29,10.77) ; R42.1 55.8,6.95 v1(55.68,6.83)
  BOTTOM w0.305: CN1.P14 v1(54.41,6.83) ; 53.47,15.18 C12.1 ; C12.1 55.55,15.18 ; C12.1 55.55,13.1 ; C12.1 53.47,13.1 ; CN1.P15 v1(55.68,6.83)
GRST#: length 17.8
  TOP w0.178: v1(32.14,20.71) 32.14,20.75 31.78,21.11 U5.4 ; v1(40.57,22.14) 40.56,24.87 39.9,25.53 U4.20
  BOTTOM w0.178: v1(40.57,22.14) 39.92,22.58 36.1,22.58 R32.1 34.31,21.83 33.19,20.71 v1(32.14,20.71)
HDD_ACT#: length 97.1
  TOP w0.178: v1(32.18,19.71) 29.74,19.71 29.14,20.31 U5.2 ; D3.2 v1(32.36,45.82) ; v1(65.03,20.85) 64.65,21.22 64.65,32.02 61.39,35.28 61.39,39.35 57.31,43.42 57.31,43.47 56.18,44.6 56.18,45.45 v1(55.79,45.84)
  BOTTOM w0.178: v1(65.03,20.85) 53.81,20.85 49.56,16.6 45.5,16.6 43.48,14.58 34.97,14.58 33.57,15.98 33.57,18.77 32.63,19.71 v1(32.18,19.71) ; v1(32.36,45.82) v1(55.79,45.84)
HS_FS_CONNECT#: length 27.4
  TOP w0.178: D5.2 25.95,43.16 v1(25.95,38.97) ; U5.15 30.79,25.51 31.63,26.35 31.63,33.21 v1(32.18,33.76)
  BOTTOM w0.178: v1(25.95,38.97) 25.95,36.43 28.11,34.27 31.54,34.27 31.6,34.21 31.6,34.21 31.86,33.94 31.86,33.94 32.05,33.76 v1(32.18,33.76)
HS_FS_SUSPEND#: length 37.7
  TOP w0.178: v3(26.68,25.83) 26.68,24.01 27.18,23.51 U5.10 ; v1(23.54,32.11) 23.54,33.38 25.32,35.16 26.84,35.16 29.64,37.95 30.14,37.95 31.03,38.84 v1(31.03,52.49) D2.2
  BOTTOM w0.178: v1(23.54,32.11) 24.05,32.11 24.68,31.47 25.45,31.47 26.04,30.89 26.04,26.64 26.68,26 v3(26.68,25.83)
ILIM1: length 1.8
  TOP w0.165: R36.1 38.28,15.98 U7.7
MISC_LED0#: length 101.8
  TOP w0.178: U5.3 29.53,20.71 30.04,20.19 32.75,20.19 v1(32.77,20.21) ; D6.2 33.53,52.49 33.83,52.18 v1(33.83,51.47) ; v1(65.2,23.22) 65.2,32.62 62.15,35.66 62.15,42.14 62.53,42.52 62.53,45.57 59.43,48.67 v1(58.21,48.67)
  BOTTOM w0.178: v1(33.83,51.47) 34.13,51.76 42.88,51.76 42.88,51.76 45.98,48.66 46.79,48.66 46.8,48.67 v1(58.21,48.67) ; v1(32.77,20.21) 33.4,20.21 34.21,19.41 34.21,16.49 35.48,15.22 43.48,15.22 45.46,17.2 49.02,17.2 55.04,23.22 v1(65.2,23.22)
MR#: length 24.1
  TOP w0.178: SW2.3 SW2.4 45.03,24.21 42.72,26.52 41.87,26.52 v1(41.81,26.57) 41.65,26.74 U4.1
  BOTTOM w0.178: R39.2 v1(41.81,26.57)
Net_92: length 1.7
  BOTTOM w0.305: 50.6,5.15 v1(50.6,6.83)
PBUTTON#: length 48.7
  TOP w0.178: v1(36.49,33.5) 35.35,33.5 34.46,32.62 34.46,31.29 32.94,29.76 32.94,29.01 34.21,27.74 34.21,26.27 31.18,23.24 29.76,23.24 29.09,23.91 U5.11 ; v1(42.46,35.92) 42.46,40.62 43.22,41.38 43.22,48.36 42.72,48.87 v1(41.32,48.87) ; SW1.4 41.28,48.91 v1(41.32,48.87) ; SW1.3 41.28,48.83 v1(41.32,48.87)
  BOTTOM w0.178: v1(41.32,48.87) 41.47,48.72 R17.2 C20.2 ; v1(36.49,33.5) 36.49,34.01 39.16,36.68 41.7,36.68 v1(42.46,35.92)
PH: length 16.7
  TOP w0.305: U3.8 50.12,38.67 v1(50.08,38.71)
  TOP w0.508: v1(50.08,38.71) 50.08,41.27 L1.2 ; U3.8 50.12,37.5 D12.2
  BOTTOM w0.305: C23.2 44.82,37.52 46.02,38.71 v1(50.08,38.71)
PWR_STATE_0: length 41.4
  TOP w0.178: U5.9 26.85,23.11 v3(26.61,23.34) ; v1(18.92,47.22) 18.71,47.42 18.71,52.17 19.73,53.19 24.04,53.19 D4.2
  BOTTOM w0.178: v1(18.92,47.22) 19.73,46.41 19.73,33.5 21.89,31.35 21.89,30.58 22.39,30.08 22.39,28.11 24.15,26.35 24.15,25.34 24.49,25 26.11,25 26.61,24.49 v3(26.61,23.34)
PWR_STATE_1: length 37.8
  TOP w0.178: D7.2 v1(24.74,45.82) ; U5.14 31.27,25.11 32.06,25.89 32.06,30.24 v1(32.21,30.36) ; v1(20.24,36.04) 22.16,36.04 v1(22.18,36.07)
  BOTTOM w0.178: v1(32.21,30.36) 29.32,33.25 27.73,33.25 25.83,35.16 23.09,35.16 v1(22.18,36.07) ; v1(24.74,45.82) 21.89,45.82 20.24,44.17 v1(20.24,36.04)
REG_5V: length 76.5
  TOP w0.635: v1(55.29,41.76) 55.29,44.5 55.22,44.5 50.92,48.8 50.92,52 L1.1 v1(46.92,52.06)
  BOTTOM w0.305: R26.2 46.67,32.77 47.13,33.23 52.97,33.23 53.67,33.93 53.67,34.56 C22.2 55.29,34.57 ; 47.61,27.44 C21.1
  BOTTOM w0.635: C21.1 47.24,28.67 49.39,30.82 53.81,30.82 55.33,32.33 55.33,34.53 55.29,34.57 v1(55.29,41.76) ; v1(46.92,52.06) 46.92,52.67 45.51,54.08 22.78,54.08 21.63,52.94 J4.3
SATA_5V: length 18.5
  TOP w0.254: U7.8 38.78,16.82 v1(38.88,16.71)
  TOP w0.305: R41.1 48.56,7.33 v1(48.06,6.83)
  TOP w0.381: C69.1 39.19,16.41 v1(38.88,16.71)
  TOP w0.762: v1(42.97,15.84) 43.42,15.84 C10.1
  BOTTOM w0.305: CN1.P8 v1(46.79,6.83) ; CN1.P9 v1(48.06,6.83)
  BOTTOM w0.635: v1(42.97,15.84) 42.96,15.85 39.74,15.85 v1(38.88,16.71)
  BOTTOM w1.524: C10.1 45.17,11.49 45.18,11.48
SATA_EN: length 27.7
  TOP w0.165: U7.5 37,20.73 36.54,21.19 R35.1
  TOP w0.178: U5.22 24.94,29.9 26.14,31.1 v1(26.14,33.56) ; v1(33.45,29.57) 35.35,27.66 R34.1 35.35,21.84 R35.1
  BOTTOM w0.178: v1(33.45,29.57) 32.3,29.57 29.13,32.74 27.6,32.74 26.78,33.56 v1(26.14,33.56)
SATARXM: length 12.1
  TOP w0.254: v1(29.19,10.52) 29.44,10.77 29.44,14.19 27.63,16.01 25.88,16.01 24.96,16.94 24.96,17.39 24.94,17.4 U5.59
  BOTTOM w0.159: C6.2 v1(29.19,10.52)
SATARXP: length 12
  TOP w0.254: v1(30.07,10.52) 29.81,10.77 29.81,14.34 27.78,16.38 26.04,16.38 25.33,17.09 25.33,17.39 25.34,17.4 U5.60
  BOTTOM w0.159: C7.2 v1(30.07,10.52)
SATATXM: length 9.9
  TOP w0.254: U5.56 23.74,17.4 23.76,17.39 23.76,16.09 24,15.84 24,14.13 25.63,12.5 25.63,10.77 v1(25.38,10.52)
  BOTTOM w0.159: C1.2 v1(25.38,10.52)
SATATXP: length 9.9
  TOP w0.254: U5.57 24.14,17.4 24.12,17.39 24.12,16.24 24.37,16 24.37,14.28 26,12.65 26,10.77 v1(26.26,10.52)
  BOTTOM w0.159: C2.2 v1(26.26,10.52)
SELF_PWR: length 3.9
  TOP w0.178: v1(29.88,24.56) 29.72,24.71 U5.13
  BOTTOM w0.178: v1(29.88,24.56) 29.88,25.4 R24.1 29.62,25.65 R25.2
SOURCE_5V: length 1.5
  TOP w0.178: U7.3 U7.2 ; 38.9,21.38 38.78,21.26
  TOP w0.254: 39.03,21.5 38.78,21.25 U7.3
  vias: v1(45.14,21.29) v1(45.91,21.29) v1(46.67,21.29) v1(47.43,21.29) v1(51.48,25.63) v1(52.24,25.63) v1(53,26.14) v1(59.48,28.42) v1(60.12,28.42) v1(60.75,28.42)
SPI_CE#: length 19.2
  TOP w0.178: U5.21 25.34,29.62 29,33.28 29,35.28 30.27,36.55 34.44,36.55 35.01,37.11 35.01,37.13 35.28,37.4 35.44,37.4 35.5,37.46 U2.1
SPI_SCK: length 31.1
  TOP w0.178: v1(31.67,35.92) 31.16,35.92 30.78,35.53 30.75,35.53 30.72,35.5 30.59,35.5 30.05,34.96 30.05,32.31 28.65,30.91 27.69,29.95 27.69,28.9 26.94,28.15 U5.17 ; U2.6 v1(40.13,41.33)
  BOTTOM w0.178: v1(40.13,41.33) 40.94,42.14 42.08,42.14 42.59,41.63 42.59,39.09 41.7,38.2 38.53,38.2 36.08,35.76 31.83,35.76 v1(31.67,35.92)
SPI_SI: length 18.5
  TOP w0.178: v1(26.76,30.33) 25.74,29.31 U5.20
  BOTTOM w0.178: J13.1 21.63,40.72 21.04,40.12 21.04,33.58 21.88,32.74 24.41,32.74 25.29,31.86 25.86,31.86 26.76,30.96 26.76,30.34 v1(26.76,30.33)
SPI_SO: length 28.2
  TOP w0.178: v1(30.56,36.06) 30.54,36.06 29.49,35.02 29.49,32.88 27.26,30.65 27.26,29.2 26.54,28.48 U5.18 ; U2.5 v1(41.4,41.33)
  BOTTOM w0.178: v1(41.4,41.33) 41.4,41.29 42.04,40.65 42.04,39.09 41.56,38.61 38.31,38.61 35.79,36.09 32.46,36.09 32.05,36.5 31,36.5 v1(30.56,36.06)
SPI_SO_J: length 21.1
  TOP w0.178: U2.2 v1(38.86,40.03)
  BOTTOM w0.178: J13.2 33.45,43.28 36.37,40.36 38.53,40.36 v1(38.86,40.03)
SS_CONNECT#: length 37.2
  TOP w0.178: U5.16 30.48,25.91 31.24,26.66 31.24,33.58 v1(31.41,33.76) ; v1(23.92,38.97) 23.92,40.74 23.41,41.25 23.41,46.08 23.79,46.46 25.44,46.46 26.08,47.09 26.08,51.28 27.28,52.48 D8.2
  BOTTOM w0.178: v1(31.41,33.76) 27.98,33.76 23.92,37.82 v1(23.92,38.97)
SSRXM: length 33.6
  TOP w0.254: J2.8 5.78,39.52 5.78,35.7 U10.1 6.08,35.4 6.08,34.26 5.74,33.93 5.74,23.13 8.54,20.34 11.25,20.34 11.61,20.7 12.03,20.7 12.39,20.34 12.88,20.34 13.24,20.7 13.69,20.7 14.05,20.34 17.39,20.34 18.15,21.09 18.42,21.09 18.43,21.11 U5.45
SSRXP: length 33.6
  TOP w0.254: U5.46 18.43,20.71 18.42,20.73 18.3,20.73 17.55,19.97 8.38,19.97 5.37,22.98 5.37,33.96 5.12,34.22 5.12,35.4 U10.2 5.41,35.69 5.41,39.18 5.41,39.25 5.41,39.44 J2.9
SSTXM: length 17.3
  TOP w0.254: U5.42 18.43,22.31 18.42,22.29 16.41,22.29 15.98,22.72 15.56,22.72 15.13,22.29 13.76,22.29 12.06,24 12.06,32.35 C13.2
SSTXP: length 17.6
  TOP w0.254: U5.43 18.53,21.91 18.49,21.88 13.66,21.88 11.69,23.85 11.69,32.31 C14.2
SW_1.1V: length 2.7
  TOP w0.178: U4.7 39.5,29.68 39.57,29.75 39.57,31.21 L2.1
SW_HB: length 33.4
  TOP w0.178: U5.8 26.94,22.71 v3(26.61,22.68) ; v1(23.16,34.27) 23.79,34.27 25.06,35.54 26.59,35.54 28.62,37.57 28.62,43.28 29.82,44.48 D1.2
  BOTTOM w0.178: v3(26.61,22.68) 26.87,22.68 27.22,23.04 27.22,26.16 27.22,26.16 27.22,26.39 28.64,27.81 28.68,27.85 28.69,27.86 28.71,27.88 28.74,27.93 29.14,28.34 29.14,28.35 29.14,29.68 29.64,30.17 29.64,31.22 28.62,32.23 27.1,32.23 26.33,33 25.95,33 24.68,34.27 v1(23.16,34.27)
TRST: length 2.8
  TOP w0.178: C68.1 43.22,27.14 41.82,27.14 41.81,27.14 40.96,27.14 40.95,27.14 U4.2
UART_RX: length 18.1
  TOP w0.178: U5.5 32.48,21.51 v1(32.78,21.21) 33.42,21.21 34.08,20.55 34.08,15.6 34.97,14.71 J1.3
UART_TX: length 19.8
  TOP w0.178: J1.2 36.49,10.14 36.49,14.2 34.46,16.23 34.46,20.85 33.69,21.62 33.2,21.62 32.91,21.91 U5.6
US_DM: length 31.3
  TOP w0.254: U5.35 21.05,25.11 21.06,25.09 21.38,25.09 v3(21.63,25.34)
  BOTTOM w0.254: J2.2 10.99,42.98 11.27,42.98 11.3,42.98 13.67,42.98 U12.1 13.89,42.75 13.89,42.37 14.45,41.82 15.09,41.82 15.6,42.32 15.6,43.04 15.78,43.22 16.96,43.22 17.76,42.43 17.76,28.61 17.76,28.56 17.81,28.5 17.81,28.5 19.08,27.23 19.13,27.18 20.27,26.05 21.31,26.05 21.63,25.73 v3(21.63,25.34)
US_DP: length 31.6
  TOP w0.254: v3(21.64,24.57) 21.5,24.73 21.06,24.73 21.05,24.71 U5.36
  BOTTOM w0.254: J2.3 11,43.35 13.68,43.35 U12.2 13.93,43.6 14.42,43.6 14.42,43.59 17.12,43.59 18.13,42.58 18.13,30.35 18.13,30.35 18.13,29.96 18.13,29.96 18.13,28.76 18.13,28.76 18.13,28.71 18.18,28.66 18.18,28.66 20.34,26.5 21.57,26.5 22.2,25.86 22.2,24.87 21.9,24.57 v3(21.64,24.57)
USB2_1P1V: length 3.7
  BOTTOM w0.305: 8.44,13.57 8.44,15.06 FB4.2 C54.1
USB_R1: length 3.8
  TOP w0.178: v1(17.85,24.81) 17.93,24.81 18.82,23.92 18.91,23.91 U5.38
  BOTTOM w0.178: R4.1 17.39,24.81 v1(17.85,24.81)
USB_R1RTN: length 2.3
  TOP w0.178: U5.39 18.65,23.51 18.51,23.53 18.4,23.64 v1(18.33,23.64)
  BOTTOM w0.178: v1(18.33,23.64) 17.92,24.05 R4.2
VSENSE: length 3.6
  TOP w0.178: U3.4 v1(42.68,33.69)
  BOTTOM w0.178: R26.1 43.58,33.68 R27.2 42.68,33.7 v1(42.68,33.69)
XI: length 10.4
  TOP w0.178: U5.52 22.14,15.9 21.23,14.99 21.23,11.61 XY1.3 22.14,10.69 22.84,10.69 C19.1 R8.2
XO: length 17.5
  TOP w0.178: U5.54 22.94,13.31 22.94,13.3 23.72,12.52 23.72,9.51 R8.1 22.98,8.26 22.57,7.85 C17.1 17.9,7.81 XY1.1
N50426: length 2.6
  TOP w0.178: U2.7 38.86,45.01 v1(38.82,45.05)
  BOTTOM w0.178: R3.2 38.8,45.04 v1(38.82,45.05)
N52215: length 3.3
  TOP w0.178: U2.3 v1(40.13,39.42)
  BOTTOM w0.178: v1(40.13,39.42) 39.92,39.22 R2.2
N191797: length 5.1
  TOP w0.178: U5.29 22.14,27.11 22.14,30.46 v1(22.65,30.96)
  BOTTOM w0.178: R5.2 23.16,30.46 v1(22.65,30.96)
N372931: length 1.4
  TOP w0.165: D1.1 R14.2
N373403: length 1.3
  TOP w0.165: D4.1 R18.2
N373877: length 1.4
  TOP w0.165: D7.1 R21.2
N388253: length 1.3
  TOP w0.165: D2.1 R15.2
N388277: length 1.4
  TOP w0.165: D5.1 R19.2
N388301: length 1.3
  TOP w0.165: D8.1 R22.2
N389292: length 1.4
  TOP w0.165: D3.1 R16.2
N389316: length 1.3
  TOP w0.165: D6.1 R20.2
N815346: length 3.8
  TOP w0.178: v1(16.43,11.15) 16.5,11.22 XY1.4
  BOTTOM w0.178: R23.2 15.61,9.69 16.43,10.5 v1(16.43,11.15)
N990729: length 2.3
  TOP w0.178: XY1.2 v1(21.61,10.11)
  BOTTOM w0.178: R37.1 21.9,9.83 v1(21.61,10.11)
N1011037: length 5.3
  TOP w0.178: R40.2 42.21,8.59 v1(40.44,6.82)
  BOTTOM w0.178: CN1.P3 v1(40.44,6.82)
N1019902: length 4.9
  TOP w0.178: v1(45.52,6.82) 46.27,7.57 R41.2
  BOTTOM w0.178: CN1.P7 v1(45.52,6.82)
N1022218: length 4.6
  TOP w0.178: 53.51,9.63 53.51,7.2 v1(53.14,6.83)
  BOTTOM w0.305: CN1.P13 v1(53.14,6.83)

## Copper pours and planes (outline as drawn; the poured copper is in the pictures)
AGND on TOP (solid shape): 40.03,19.6 40.56,19.6 40.56,19.35 40.03,19.35 40.03,19.1 40.56,19.1 40.56,18.85 40.03,18.85 40.03,18.38 37.53,18.38 37.53,18.85 37.01,18.85 37.01,19.1 37.53,19.1 37.53,19.35 37.01,19.35 37.01,19.6 37.53,19.6 37.53,20.08 40.03,20.08
AGND on TOP: 61.56,2.72 61.16,3.69 60.2,4.12 19.39,4.12 18.44,3.67 18.05,2.69 18.05,0.76 0.76,0.76 0.76,54.24 69.24,54.24 69.24,0.76 61.56,0.76
AGND on BOTTOM: 38.17,26.6 40.81,26.6 40.81,26.62 46.07,26.62 46.07,26.65 47.14,26.65 49.72,29.22 56.31,29.22 57.51,30.43 57.51,38.75 57.53,38.77 44.74,38.77 42.99,37.02 42.99,32.39 42.48,32.39 42.48,29.83 39.58,29.83 39.58,29.59 38.17,29.59
AGND on BOTTOM: 48.81,6.45 52.37,6.45 52.37,17.38 49.32,17.38 46.68,14.73 46.68,13.16 48.81,11.03
AGND on BOTTOM: 22.28,21.55 24.81,21.55 26.12,21.56 26.36,21.86 26.94,21.87 26.94,22.73 26.14,23.54 26.14,24.62 24.5,26.25 22.28,26.25
AGND on BOTTOM: 0.68,0.61 0.68,43.41 6.27,43.41 6.27,45.32 6.39,45.44 9.19,45.44 9.19,44.43 19.35,44.43 19.35,28.93 21.25,27.03 21.25,18.9 19.48,18.9 19.22,19.15 19.22,23.34 14.9,23.34 14.78,23.47 14.78,19.66 9.06,19.66 9.06,17.74 8.87,17.74 8.87,15.69 9.06,15.69 9.06,0.61 ; 1 cut-out
GND_EARTH on TOP, BOTTOM: 18.46,54.28 0.68,54.28 0.68,44.53 6.14,44.53 6.14,45.7 9.44,45.7 9.44,44.72 18.46,44.72
VDD_1P1V on BOTTOM: 42.72,32.74 42.72,36.43 21.06,36.43 21.06,28.61 21.61,28.07 21.61,23.07 21.58,23.1 21.58,17.96 19.75,17.96 19.7,17.91 18.13,19.48 18.13,23.59 15.16,23.59 15.16,19.28 10.2,19.28 10.2,18.9 9.44,18.9 9.44,0.61 18.08,0.61 18.08,3.91 23.41,3.91 23.41,6.45 32.05,6.45 32.05,3.91 33.32,3.91 33.32,21.57 34.46,22.71 34.46,28.68 35.73,28.68 35.73,30.71 36.87,30.71 38.91,32.74 ; 1 cut-out
VDDA_3P3V on TOP: 17.01,18.12 16.35,18.72 16.07,18.71 16.07,18.69 14.04,18.69 14.04,19.79 16.07,19.79 16.07,19.29 19.07,19.29 19.07,18.12
VDDA_3P3V on TOP: 15.1,23.28 15.1,38.42 18.33,38.42 18.33,38.12 22.15,38.12 22.15,36.71 18.33,36.71 18.33,25.21 17.22,25.21 17.22,23.28
VSSOSC on TOP: 17.11,11.91 17.11,7.6 22.68,7.6 22.68,12.57 19.73,12.57 19.07,11.91
VSSOSC on TOP: 21.53,14.48 21.53,12.02 21.63,12.02 22.68,10.97 23.08,10.97 23.08,9.35 23.03,9.3 23.97,9.3 23.97,11.89 22.62,13.23 22.62,14.48
VSSOSC on BOTTOM: 15.41,7.47 22.65,7.47 23.67,8.49 23.67,12.55 19.73,12.55 19.09,11.91 15.41,11.91
BOARD_3P3V on BOTTOM: 41.07,6.45 41.07,10.9 42.21,10.9 49.07,17.76 61,17.76 60.98,22.66 58.73,26.66 58.73,39.78 52.6,47.71 52.63,49.46 52.63,49.82 25.15,49.84 23.67,48.34 23.16,47.83 23.16,39.6 23.92,39.6 23.92,38.33 26.97,38.33 28.49,36.81 35.8,36.81 38.08,39.08 57.84,39.08 57.84,30.17 56.42,28.75 50.82,28.75 48.32,26.26 37.12,26.26 37.12,27.92 36.24,27.92 36.24,20.3 34.72,20.3 34.72,6.45
BOARD_12V on BOTTOM: 63.54,0.48 69.13,0.48 69.13,43.59 63.19,43.59 63.04,42.65 62.26,41.4 62.25,41.15 62.25,17.76 63.54,17.76
FUSE_12V on BOTTOM: 52.75,6.45 56.43,6.45 56.43,4.17 63.04,4.17 63.04,17.38 52.75,17.38
Net_16 on BOTTOM (solid shape): 8.68,7.81 9.1,5.79 9.08,5.7 9.03,5.63 8.6,5.62 8.53,5.94 8.11,7.76 8.68,7.81
Net_17 on BOTTOM (solid shape): 11.48,6.84 13.13,6.84 13.55,6.84 13.2,6.39 12.89,5.96 12.7,5.54 12.5,5.24 12.36,5.11 12.16,5.03 12.05,5.01 11.93,5.12 11.85,5.24 11.77,5.28 11.6,5.32 11.33,5.33 11.12,5.24 10.94,5.05 10.73,4.53 10.4,3.74 9.95,3.09 9.44,2.72 9.05,2.53 8.79,2.43 8.53,2.35 8.17,2.29 8.38,2.72 8.5,3.37 8.25,3.93 7.49,4.58 6.53,4.99 6.42,5.25 6.35,5.97 6.36,6.3 6.43,6.66 6.51,6.81 6.56,6.92 6.62,7.45 6.6,7.67 6.65,7.75 6.87,7.83 7.29,7.92 7.5,7.91 7.7,7.87 7.93,7.78 8.07,7.2 7.57,7.2 7.74,6.62 8.24,6.62 8.38,5.87 8.34,5.7 8.24,5.68 8.11,5.69 8.02,5.76 8.18,4.96 8.35,4.9 8.39,4.9 8.61,4.88 8.76,4.91 9,5.05 9.13,5.29 9.22,5.67 9.22,5.96 9.11,6.65 9.71,6.65 9.55,7.2 8.97,7.2 8.83,7.91 9.04,7.95 9.25,8.05 9.36,8.17 9.44,8.36 9.44,9.6 11.48,9.6
SATA_5V on BOTTOM: 48.43,6.45 48.43,12.07 44.04,12.07 42.13,10.16 42.13,6.45
SOURCE_5V on TOP: 50.02,24.77 50.02,26.1 52.09,26.1 52.09,26.7 57.21,26.7 57.21,28.28 58.51,28.28 58.51,29.18 61.02,29.18 61.02,28.28 61.68,28.28 61.68,25.94 59.21,25.94 59.21,25.89 53.28,25.89 53.28,24.77
SOURCE_5V on TOP: 38.63,20.35 38.63,23.09 39.4,23.09 39.4,22.16 40.14,22.16 40.14,21.92 40.37,21.69 40.88,21.69 40.88,21.7 41.13,21.94 48.18,21.94 48.18,20.66 45.65,20.65 40.62,20.65 40.08,21.19 40.08,21.43 39.4,21.43 39.4,20.35
SOURCE_5V on BOTTOM: 44.83,20.51 48.78,20.51 53.31,25.04 53.31,26.62 53.26,26.67 51.67,26.67 48.62,23.61 48.62,22.63 44.9,22.63 44.85,22.67 44.83,22.65
SOURCE_5V on BOTTOM: 59.1,27.99 59.1,40.4 59.09,40.4 58.52,41.06 53.62,47.4 53.58,50.44 25.2,50.5 22.74,48.04 22.74,48.08 22.72,48.02 19.41,48.02 19.41,53.99 48.35,53.99 48.35,53.97 61.78,53.97 69.17,53.99 69.14,44.1 63.01,44.08 61.8,41.89 61.78,27.99

Small or netless copper shapes (teardrops, artwork), in the pictures only: 1 on BOTTOM

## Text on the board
BOTTOM: Layer 2 - Secondary Side | 12
Ref Des/Assembly Bottom: Assembly | 2
Board Geometry/Soldermask Bottom: Soldermask - Secondary Side | 16
Ref Des/Silkscreen Bottom: MADE IN U.S.A. | GPIO7 (D8):SS_CONNECT# | GPIO2 ( D2) :HS_FS_SUSPEND# | GPIO6 (D5): HS_FS_CONNECT# | GPIO5 (D7):PWR_STATE_1 | GPIO0 (D1): SW_HB | GPIO1 ( D4) :PWR_STATE_0 | GPIO3 (SW1) : PBUTTON# | GPIO4: SELF_PWR | 16 | PWM0 (D3): HDD_ACT# | PWM1 (D6): MISC_LEDO# | GPIO10: SATA_EN | GPIO11: FAULT# | GPIO9:UART_TX | GPIO8:UART_RX | Silkscreen - Secondary Side | 14 | TUSB9261DEMO PVP PG2.X REV B | 33 | 48 | 32 | 49 | 64 | 17 | 1 | SN
User.Comments: DEMO PVP
TOP: Layer 1 - Primary Side | 1
Ref Des/Assembly Top: Assembly | 1 | 2
Board Geometry/Soldermask Top: Soldermask - Primary Side | 15
Ref Des/Silkscreen Top: GLOBAL RESET | SELF_PWRED | VBUS | BUS_PWRED | Silkscreen - Primary Side | 13 | RX | TX | - | +
DIMENSION: Solderpaste - Primary Side | NON PLATED ALIGNMENT HOLE | 17 | 2X 0.85MM+/-0.025MM | DRILL DRAWING | 19 | PRIMARY SIDE VIEW
DISPLAY_BOTTOM: Solderpaste - Secondary Side | 18
User.13: PLUG LAYER SECONDARY OPERATION | 17
User.15: LAYER 1 | LAYER 6 | BOTTOM | TOP | CORE 0.060" 1/2 OZ/1/2 OZ | GENERAL NOTES:               TUSB9261 (ESPRESSO) DEMO PVP 1213 REV A | PROCESS NOTES: | TRACE WIDTHS AND ROUTING: | DRILL NOTES: | BEST INDUSTRY PRACTICE IPC-A-600C (COMMERCIAL STANDARD). | OVER 50 - 80 MICRO INCH NICKEL. | OTHERWISE SPECIFIED. | 4: INTERNAL LAYER SIGNLE ENDED 50 OHM TRACE WIDTH: 5.25 MILS. | 1: ALL FABRICATION ITEMS MUST MEET OR EXCEED | 2: LAMINATE MATERIAL: FR4 | 3: COPPER WEIGHT: 1 OZ OUTER LAYERS, 1 OZ INNER LAYERS. | 4: FINISH BOARD THICKNESS: 62 MILS MAX. | 5: POSITION ACCURACY: +/- .0015 INCH. | 6: WARP AND TWIST NOT TO EXCEED .020/ INCH. | 7: CONTROLLED IMPEDANCE LAYERS: TOP AND BOTTOM. | 8: LAYER COUNT:2. | 9: VIAS PADS FOR ALL UNUSED INTERNAL SIGNAL LAYERS BE REMOVED DURING BOARD | MANUFACTURING. | 1: COPPER PLATING TO BE 0.001 MINIMUM INCH PLATED THROUGH HOLES. | 2: CIRCUITRY ON OUTER LAYERS TO BE PLATED WITH 7-12 MICRO INCH GOLD | 3: SOLDERMASK BOTH SIDE: RED. | 4: APPLY WHITE SILKSCREEN TO TOP AND BOTTOM SIDE OF BOARD USING | 5: ALL GROUND AND POWER PLANES HELD BACK .020 INCH MINIMUM FROM EDGE OF BOARD. | 1: TRACE WIDTH CALCULATIONS ARE STARTING VALUES. BOARD SHOP MAY | ADJUST TRACE WIDTHS TO COMPENSATE FOR PROCESS. PLEASE SUBMIT | FINAL CALCULATIONS WITH ESTIMATE. | 2: DIELECTRIC CONSTANT:4.1 | 3: EXTERNAL LAYER SINGLE ENDED 50 OHM TRACE WIDTH: 7.0 MILS. | 1: DRILL SIZES 18 MILS AND SMALLER ARE EXACT. | 2: DRILL SIZES 20 MILS AND ABOVE - TOLERANCE:-0.0/ +.004 INCH UNLESS | 3: UNPLATED HOLES- TOLERANCE: +.001/-.002 INCH. | 90 OHM DIFFERENTIAL PAIR TRACE WIDTH: 10.0 MILS;  SPACING: 4.50 MILS. | 100 OHM DIFFERENTIAL PAIR TRACE WIDTH: 5.0 MILS;  SPACING: 8.25 MILS. | SEPARATE ARTWORK.
User.25: FIGURE | SIZE | 6.0 | 8.0 | 8.1 | 12.0 | 28.0 | 36.0 | 37.0 | 40.0 | 42.0 | 91.0 | 120.0 | 140.0 | 33.4 | 47.24 | 63.3 | 76.77 | 125.0 | DRILL CHART: TOP to BOTTOM | ALL UNITS ARE IN MILS | TOLERANCE | +0.0/-0.0 | +3.0/-3.0 | +2.0/-2.0 | +1.0/-1.0 | +1.97/-0.0 | +1.97/-1.97 | PLATED | NON-PLATED | QTY | 1 | 224 | 17 | 11 | 5 | 8 | 4 | 2 | 6
